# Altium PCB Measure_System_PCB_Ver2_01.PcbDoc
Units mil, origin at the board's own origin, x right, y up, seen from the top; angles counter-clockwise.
Board outline 2670.03 x 2130.03 mil, 2 copper layers (Top Layer, Bottom Layer); 49 components, 31 nets, 143 pads, 4 vias.
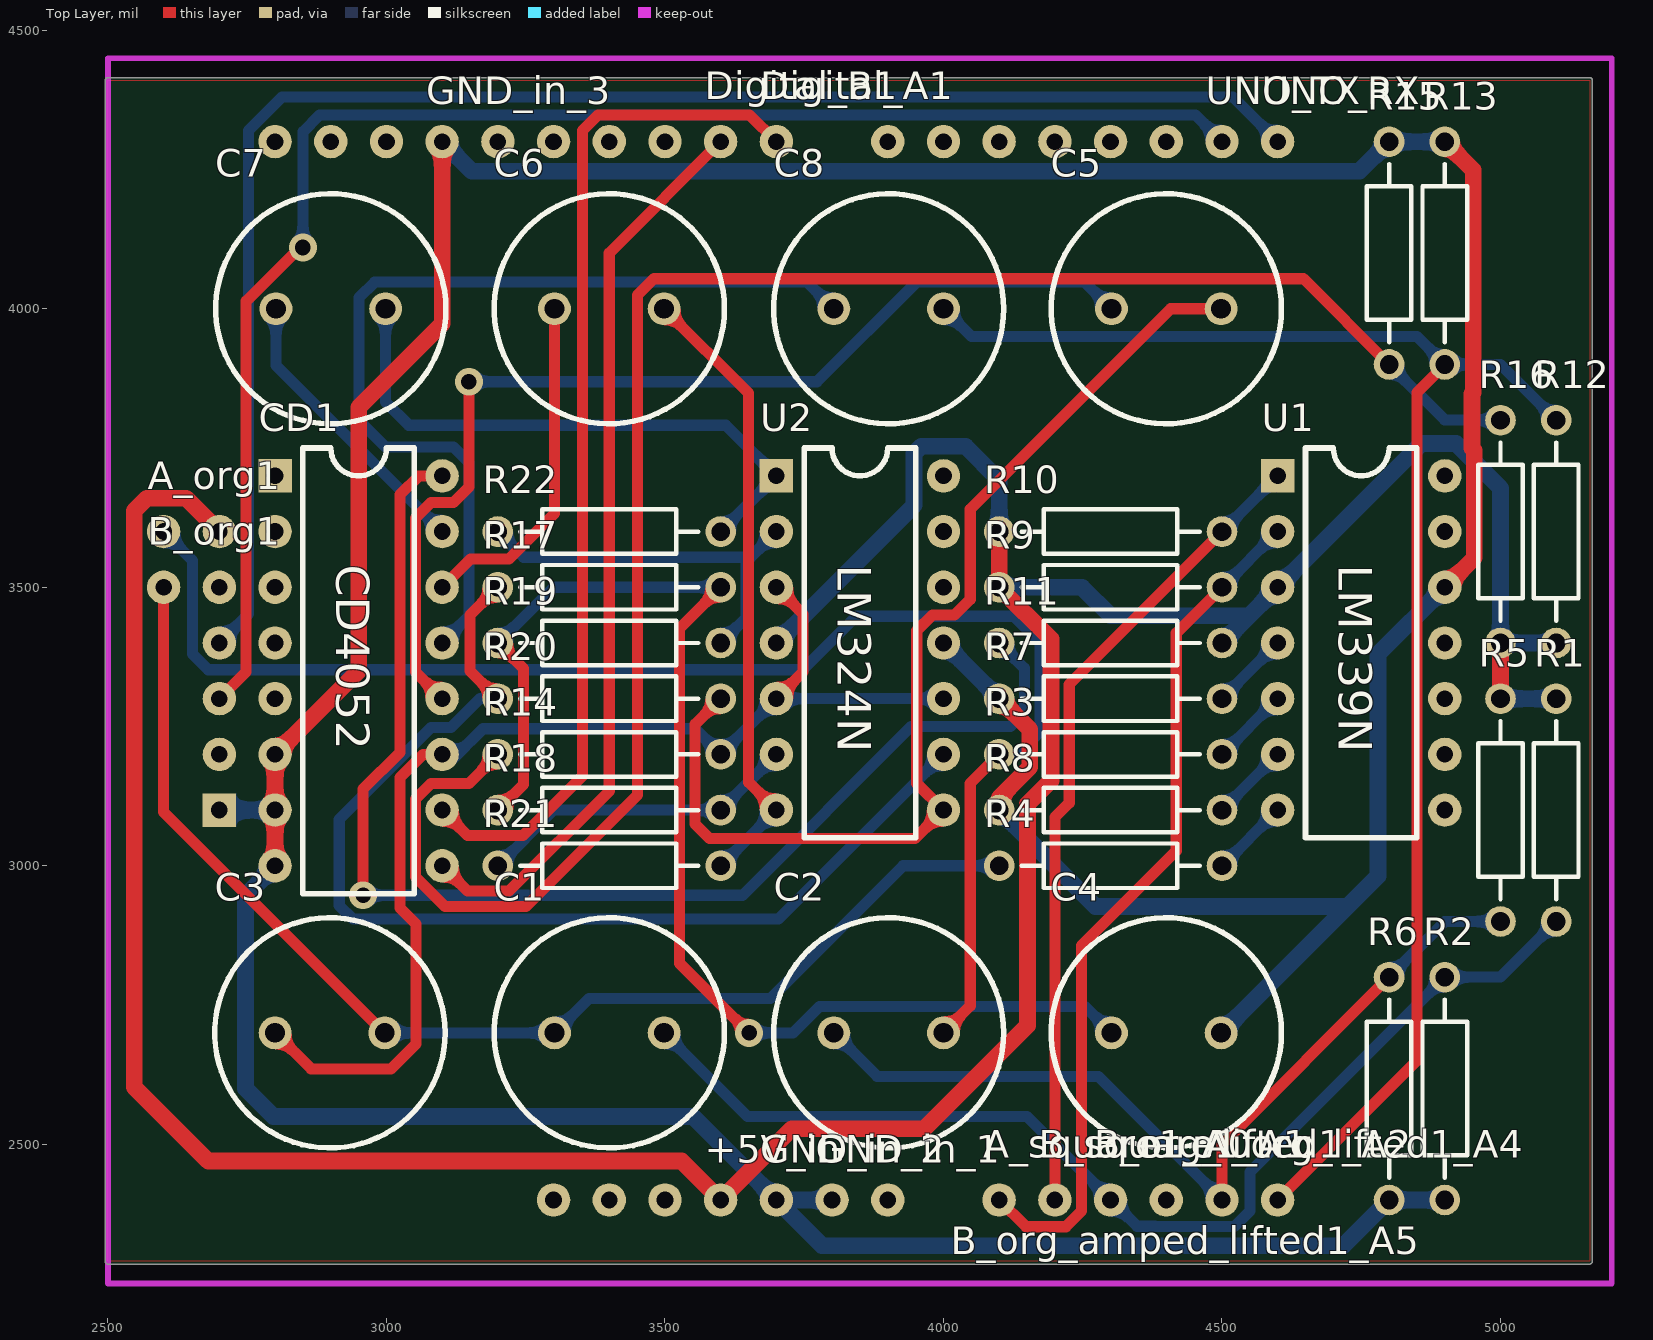
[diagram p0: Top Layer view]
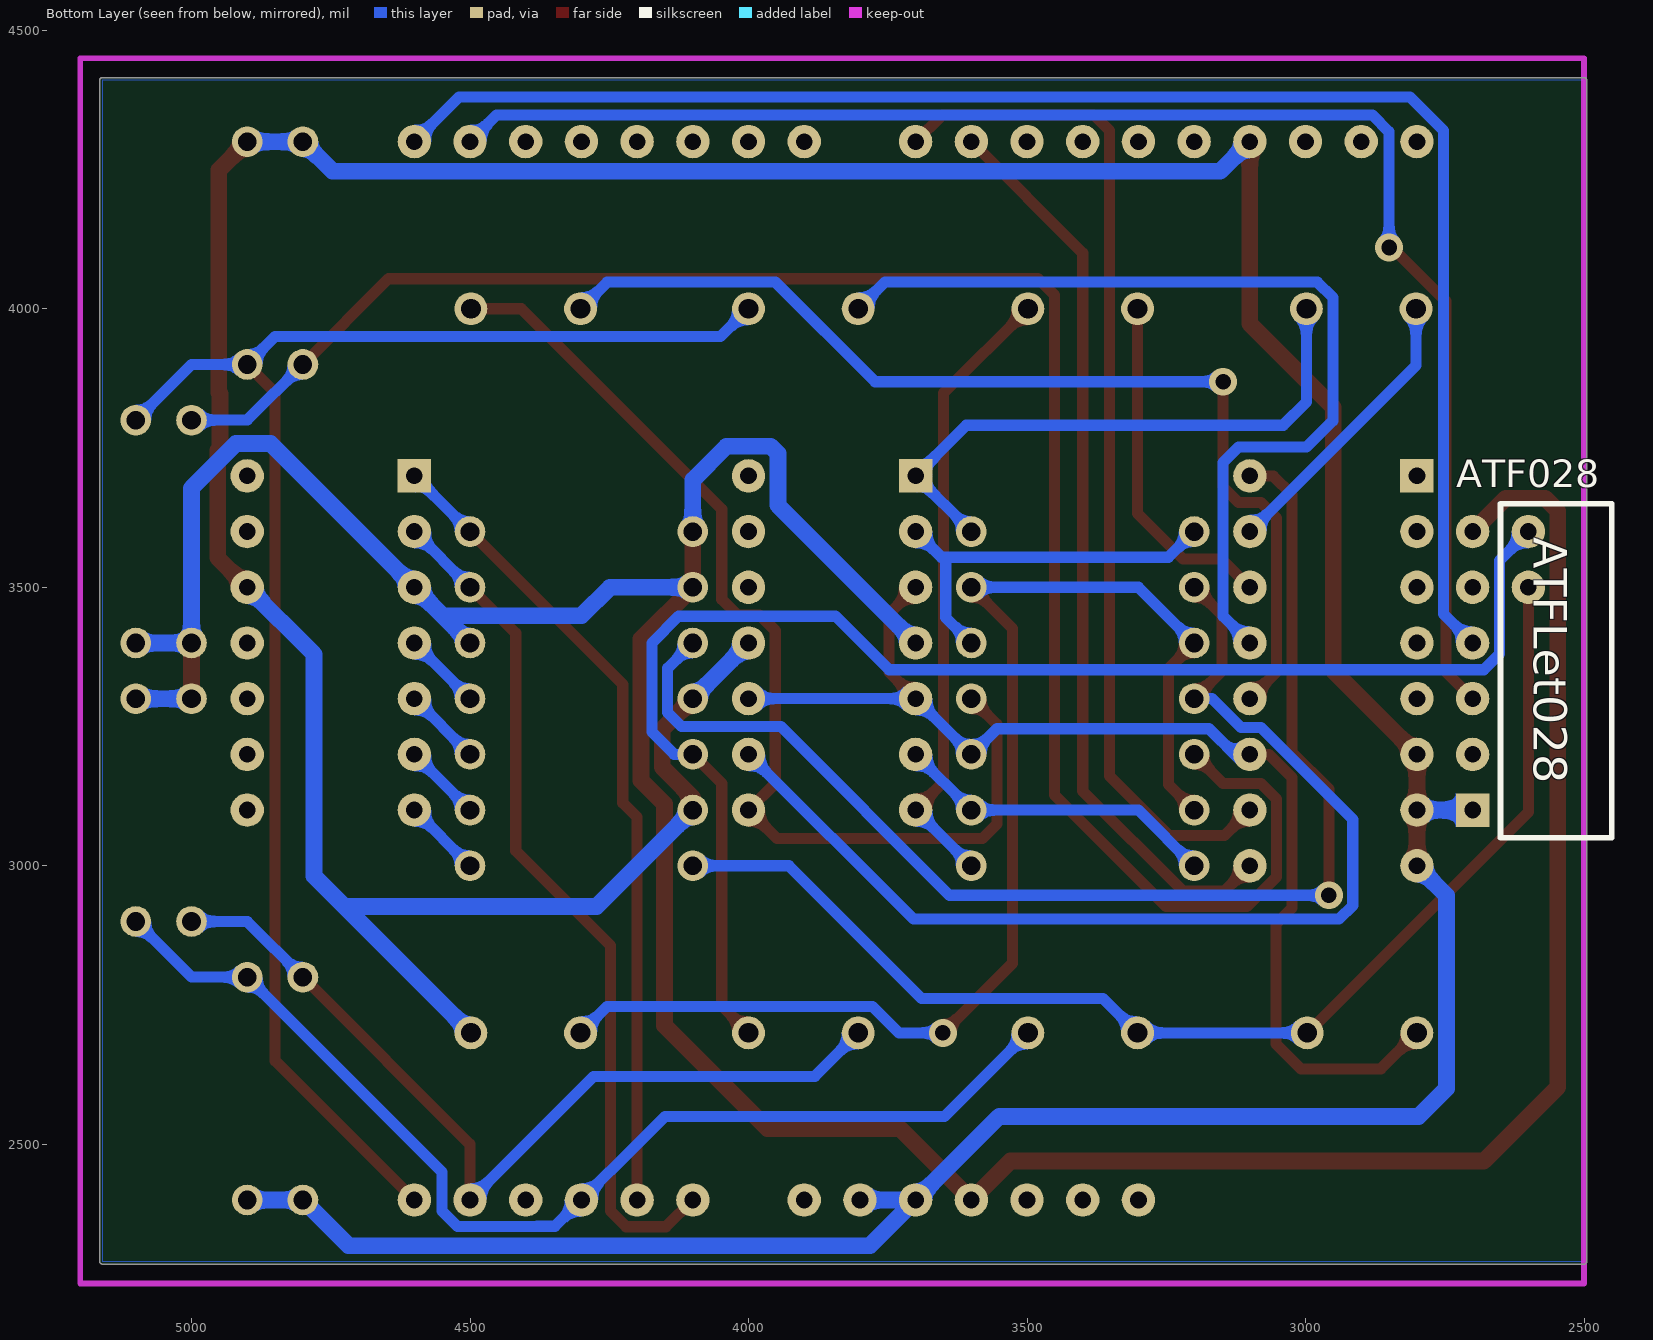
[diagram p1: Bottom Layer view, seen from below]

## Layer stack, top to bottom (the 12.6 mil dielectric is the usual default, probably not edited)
Top Solder: solder mask 0.4, Solder Resist, Dk 3.5
Top Layer: signal copper 1.4
Dielectric 1: dielectric 12.6, FR-4, Dk 4.8
Bottom Layer: signal copper 1.4
Bottom Solder: solder mask 0.4, Solder Resist, Dk 3.5

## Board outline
2494.99,2290 ccw(c2500,2290) 2500,2284.99 5160,2284.99 ccw(c5160,2290) 5165.02,2290 5165.02,4410 ccw(c5160,4410) 5160,4415.02 2500,4415.02 ccw(c2500,4410) 2494.99,4410

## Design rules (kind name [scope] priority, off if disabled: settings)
Clearance [All] p1: gap=7.87 ignorepadtopadclearanceinfootprint=FALSE
PolygonConnect [All] p1: connectstyle=Relief reliefconductorwidth=10 reliefentries=4 polygonreliefangle="90 Angle" airgapwidth=10
RoutingVias [All] p1: holewidth=28 width=50 viastyle="Through Hole" minholewidth=28 minwidth=50 maxholewidth=28 maxwidth=50
SolderMaskExpansion [All] p1: expansion=4 istentingtop=FALSE
Width Width_2 [InNet('GND')] p1: maxlimit=50 minlimit=10 preferedwidth=30 minimp=50.000000 maximp=50.000000 favimp=50.000000
Width Width_1 [InNet('+5')] p2: maxlimit=50 minlimit=10 preferedwidth=30 minimp=50.000000 maximp=50.000000 favimp=50.000000
Width [All] p3: maxlimit=50 minlimit=10 preferedwidth=20
30 further rules are at their usual default settings.

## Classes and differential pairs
component class Part_Square: C1 C2 R1 R2 R3 R4 R5 R6 R7 R8 R9 R10 U1
component class Part_PGA: C3 C4 C5 C6 C7 C8 CD1 R11 R12 R13 R14 R15 R16 R17 R18 R19 R20 R21 R22 U2
component class Measure_System_Main: +5V_in A_org1 A_org_lifted1_A4 A_square1_A0 ATF028 B_org1 B_org_amped_lifted1_A5 B_org_lifted1_A2 B_square1_A1 Digital_A1 Digital_B1 GND_in_1 GND_in_2 GND_in_3 UNO_RX UNO_TX

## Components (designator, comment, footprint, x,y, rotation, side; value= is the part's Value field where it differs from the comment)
+5V_in "Hole" Hole 3600,2400 r90 top
A_org1 "Hole" Hole 2600,3600 r90 top
A_org_lifted1_A4 "Hole" Hole 4500,2400 r90 top
A_square1_A0 "Hole" Hole 4100,2400 r90 top
ATF028 "ATFLet028" ATFLet028 2700,3600 r180 bottom
B_org1 "Hole" Hole 2600,3500 r90 top
B_org_amped_lifted1_A5 "Hole" Hole 4600,2400 r90 top
B_org_lifted1_A2 "Hole" Hole 4300,2400 r90 top
B_square1_A1 "Hole" Hole 4200,2400 r90 top
C1 "Cap Pol1" RB5-10.5 3400,2700 r0 top value=10u
C2 "Cap Pol1" RB5-10.5 3901.58,2700 r180 top value=10u
C3 "Cap Pol1" RB5-10.5 2898.43,2700 r180 top value=10u
C4 "Cap Pol1" RB5-10.5 4400,2700 r180 top value=10u
C5 "Cap Pol1" RB5-10.5 4400,4000 r180 top value=10u
C6 "Cap Pol1" RB5-10.5 3400,4000 r180 top value=10u
C7 "Cap Pol1" RB5-10.5 2900,4000 r180 top value=10u
C8 "Cap Pol1" RB5-10.5 3901.57,4000 r0 top value=10u
CD1 "CD4052" CD4052 2800,3700 r0 top
Digital_A1 "Hole" Hole 3700,4300 r90 top
Digital_B1 "Hole" Hole 3600,4300 r90 top
GND_in_1 "Hole" Hole 3800,2400 r90 top
GND_in_2 "Hole" Hole 3700,2400 r90 top
GND_in_3 "Hole" Hole 3100,4300 r90 top
R1 "Res2" AXIAL-0.4 5100,3100 r90 top value=100k
R2 "Res2" AXIAL-0.4 4900,2600 r90 top value=100k
R3 "Res2" AXIAL-0.4 4300,3200 r180 top value=1k
R4 "Res2" AXIAL-0.4 4300,3000 r180 top value=1k
R5 "Res2" AXIAL-0.4 5000,3100 r90 top value=100k
R6 "Res2" AXIAL-0.4 4800,2600 r90 top value=100k
R7 "Res2" AXIAL-0.4 4300,3300 r0 top value=10k
R8 "Res2" AXIAL-0.4 4300,3100 r180 top value=10k
R9 "Res2" AXIAL-0.4 4300,3500 r0 top value=10k
R10 "Res2" AXIAL-0.4 4300,3600 r180 top value=10k
R11 "Res2" AXIAL-0.4 4300,3400 r0 top value=200
R12 "Res2" AXIAL-0.4 5100,3600 r270 top value=100k
R13 "Res2" AXIAL-0.4 4900,4100 r270 top value=100k
R14 "Res2" AXIAL-0.4 3400,3200 r0 top value=100k
R15 "Res2" AXIAL-0.4 4800,4100 r270 top value=100k
R16 "Res2" AXIAL-0.4 5000,3600 r90 top value=100k
R17 "Res2" AXIAL-0.4 3400,3500 r180 top value=50k
R18 "Res2" AXIAL-0.4 3400,3100 r0 top value=24k
R19 "Res2" AXIAL-0.4 3400,3400 r0 top value=12k
R20 "Res2" AXIAL-0.4 3400,3300 r0 top value=100k
R21 "Res2" AXIAL-0.4 3400,3000 r0 top value=100k
R22 "Res2" AXIAL-0.4 3400,3600 r0 top value=100k
U1 "LM339N" LM339N 4600,3700 r0 top
U2 "LM324N" LM324N 3700,3700 r0 top
UNO_RX "Hole" Hole 4600,4300 r90 top
UNO_TX "Hole" Hole 4500,4300 r90 top

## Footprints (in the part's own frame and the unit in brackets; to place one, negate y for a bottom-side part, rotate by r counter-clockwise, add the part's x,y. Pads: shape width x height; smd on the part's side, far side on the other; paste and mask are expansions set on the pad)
ATFLet028 [mil]
  rect 60x60 hole 30: 1(0,-500)
  round 60 hole 30 mask+4: 2(0,-400) 3(0,-300) 4(0,-200) 5(0,-100) 6(0,0)
  silkscreen extent 50,-550 250,50
AXIAL-0.4 [mm] "Axial Device, Thru-Hole; 2 Leads; 0.4 in Pin Spacing"
  round 1.4 hole 0.85: 1(-5.08,0) 2(5.08,0)
  silkscreen extent -4.06,-1.02 4.06,1.02
CD4052 [mil]
  rect 60x60 hole 30: 1(0,0)
  round 60 hole 30 mask+4: 2(0,-100) 3(0,-200) 4(0,-300) 5(0,-400) 6(0,-500) 7(0,-600) 8(0,-700) 9(300,-700) 10(300,-600) 11(300,-500) 12(300,-400) 13(300,-300) 14(300,-200) 15(300,-100) 16(300,0)
  silkscreen extent 50,-750 250,50
Hole [mil]
  round 60 hole 30 mask+4: 1(0,0)
LM324N [mil]
  rect 60x60 hole 30: 1(0,0)
  round 60 hole 30 mask+4: 2(0,-100) 3(0,-200) 4(0,-300) 5(0,-400) 6(0,-500) 7(0,-600) 8(300,-600) 9(300,-500) 10(300,-400) 11(300,-300) 12(300,-200) 13(300,-100) 14(300,0)
  silkscreen extent 50,-650 250,50
LM339N [mil]
  rect 60x60 hole 30: 1(0,0)
  round 60 hole 30 mask+4: 2(0,-100) 3(0,-200) 4(0,-300) 5(0,-400) 6(0,-500) 7(0,-600) 8(300,-600) 9(300,-500) 10(300,-400) 11(300,-300) 12(300,-200) 13(300,-100) 14(300,0)
  silkscreen extent 50,-650 250,50
RB5-10.5 [mm] "Capacitor (Radial); 2 Leads"
  round 1.5 hole 0.9: 1(-2.5,0) 2(2.5,0)
  silkscreen extent -5.25,-5.25 5.25,5.25

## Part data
C1 C2 C3 C4 C5 C6 C7 C8: "Polarized Capacitor (Radial)"
R1 R2 R3 R4 R5 R6 R7 R8 R9 R10 R11 R12 R13 R14 R15 R16 R17 R18 R19 R20 R21 R22: "Resistor"

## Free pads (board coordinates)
  round 60 hole 30 mask+4: 5(4400,2400) 7(3900,2400) 8(3500,2400) 9(3400,2400) 10(3300,2400) 11(4400,4300) 12(4300,4300) 13(4200,4300) 14(4100,4300) 15(4000,4300) 16(3900,4300) 17(3500,4300) 18(3400,4300) 19(3300,4300) 20(3200,4300) 22(3000,4300) 23(2900,4300) 24(2800,4300)

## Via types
v1: diameter 50, hole 28, Top Layer to Bottom Layer, 4 vias

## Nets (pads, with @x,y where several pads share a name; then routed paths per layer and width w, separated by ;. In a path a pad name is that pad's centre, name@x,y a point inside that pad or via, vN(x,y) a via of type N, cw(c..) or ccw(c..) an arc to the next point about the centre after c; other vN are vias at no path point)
+5: +5V_in.1 ATF028.6 R1.2 R5.2 R9.1 R10.2 R11.2 R12.2 R16.1 U1.3 U2.4 | length 6430
  Top Layer w30: ATF028.6 2640,3660 2570,3660 2547,3637 2547,2603 2680,2470 3530,2470 +5V_in.1 3728,2528 3966,2528 4151,2713 4151,3111 4192.87,3152.87 4192.87,3407.13 R9.1 R10.2 ; R5.2 R16.1
  Bottom Layer w30: U2.4 3947,3647 3947,3740 3960,3753 4040,3753 4100,3693 R10.2 ; R9.1 4249,3500 4300,3449 4549,3449 ; R11.2 4549,3449 ; R5.2 R1.2 ; R12.2 R16.1 5000,3678 4920,3758 4858,3758 U1.3 4549,3449
B_org: B_org1.1 C1.1 C3.1 R4.2 | length 2191.8
  Top Layer w20: B_org1.1 2600,3096.85 C3.1
  Bottom Layer w20: C3.1 C1.1 3363.57,2762 3689.32,2762 3927.32,3000 R4.2
B_org_amp_1: C3.2 CD1.11 R14.2 U2.3 U2.5 U2.10 | length 2101.1
  Top Layer w20: C3.2 2865,2635 3008,2635 3053,2680 3053,2895.25 3024.25,2924 3024.25,3158.25 3066,3200 CD1.11 ; U2.5 3748,3348 3748,3452 U2.3
  Bottom Layer w20: CD1.11 3127,3200 3173,3246 3554,3246 R14.2 U2.5 U2.10
B_org_amp_2.5: C5.2 CD1.12 | length 1899.6
  Top Layer w20: CD1.12 3052.13,3347.87 3052.13,3624.13 3080,3652 3120,3652 3148,3680 v1(3148,3869)
  Bottom Layer w20: v1(3148,3869) 3773,3869 3952,4048 4253.57,4048 C5.2
B_org_amp_5: C6.2 CD1.14 | length 623.9
  Top Layer w20: CD1.14 3151,3551 3220,3551 3301.57,3632.57 C6.2
B_org_amp_10: C7.2 CD1.15 | length 523.6
  Bottom Layer w20: C7.2 2801.58,3898.42 CD1.15
B_org_amped: C8.1 CD1.13 | length 1676.6
  Bottom Layer w20: CD1.13 3148,3448 3148,3724 3120,3752 2998,3752 2951,3799 2951,4020 2979,4048 3755.15,4048 C8.1
Digital_A: CD1.10 Digital_A1.1 | length 1853.1
  Top Layer w20: CD1.10 3145.43,3054.57 3245,3054.57 3352,3161.57 3352,4320 3380,4348 3652,4348 Digital_A1.1
Digital_B: CD1.9 Digital_B1.1 | length 1641.7
  Top Layer w20: CD1.9 3145.43,2954.57 3220,2954.57 3400,3134.57 3400,4100 Digital_B1.1
GND: ATF028.1 C4.1 CD1.6 CD1.7 CD1.8 GND_in_1.1 GND_in_2.1 GND_in_3.1 R2.1 R6.1 R7.1 R8.2 R13.1 R15.1 U1.12 U2.11 | length 9089.9
  Top Layer w30: CD1.8 CD1.7 CD1.6 2950,3350 2950,3823 3100,3973 GND_in_3.1 ; R8.2 4100,3122 4155,3177 4155,3245 R7.1 ; U1.12 4953,3553 4953,3746 4949,3750 4949,3847 4951,3849 4951,4249 R13.1
  Bottom Layer w30: ATF028.1 CD1.7 ; CD1.8 2747,2947 2747,2600 2797,2550 3550,2550 GND_in_2.1 ; GND_in_3.1 3153,4247 4747,4247 R15.1 R13.1 ; GND_in_1.1 GND_in_2.1 ; U2.11 R7.1 ; R8.2 4273,2927 4725.43,2927 ; C4.1 4725.43,2927 ; R2.1 R6.1 4718,2318 3782,2318 GND_in_2.1 ; U1.12 4780,3380 4780,2981.57 4725.43,2927
NetA_org1_1: A_org1.1 C2.1 R3.2 | length 2625.4
  Top Layer w20: C2.1 4048,2748 4048,3148 R3.2
  Bottom Layer w20: A_org1.1 2652,3548 2652,3380 2680,3352 3748,3352 3844,3448 4125.31,3448 4173.31,3400 4173.31,3240 4133.31,3200 R3.2
NetA_org_lifted1_A4_1: A_org_lifted1_A4.1 C2.2 R5.1 R6.2 | length 1586.8
  Top Layer w20: A_org_lifted1_A4.1 4500,2500 R6.2
  Bottom Layer w20: C2.2 3881.15,2622 4278,2622 A_org_lifted1_A4.1 ; R6.2 4900,2900 R5.1
NetA_square1_A0_1: A_square1_A0.1 R9.2 U1.2 | length 1545.3
  Top Layer w20: A_square1_A0.1 4148,2352 4220,2352 4248,2380 4248,2857 4418,3027 4418,3418 R9.2
  Bottom Layer w20: R9.2 U1.2
NetATF028_3: ATF028.3 UNO_TX.1 | length 2765.4
  Top Layer w20: ATF028.3 2748,3348 2748,4013.46 2844.54,4110 v1(2850,4110)
  Bottom Layer w20: v1(2850,4110) 2850,4317.7 2880.17,4347.87 4452.13,4347.87 UNO_TX.1
NetATF028_4: ATF028.4 UNO_RX.1 | length 2847.4
  Bottom Layer w20: ATF028.4 2752.13,3452.13 2752.13,4319.83 2812.3,4380 4520,4380 UNO_RX.1
NetB_org_amped_lifted1_A5_1: B_org_amped_lifted1_A5.1 C8.2 R12.1 R13.2 | length 2807.1
  Top Layer w20: B_org_amped_lifted1_A5.1 4850,2650 4850,3850 R13.2
  Bottom Layer w20: C8.2 4050,3950 4850,3950 R13.2 5000,3900 R12.1
NetB_org_lifted1_A2_1: B_org_lifted1_A2.1 C1.2 R1.1 R2.2 | length 2013.6
  Bottom Layer w20: C1.2 3648.43,2550 4150,2550 4347.13,2352.87 4379.42,2352.87 4380.17,2352.13 4522.13,2352.13 4550,2380 4550,2450 R2.2 5000,2800 R1.1
NetB_square1_A1_1: B_square1_A1.1 R10.1 U1.1 | length 1465.7
  Top Layer w20: B_square1_A1.1 4200,3087.25 4225.75,3113 4225.75,3325.75 R10.1
  Bottom Layer w20: R10.1 U1.1
NetC4_2: C4.2 R17.1 R18.1 R19.1 | length 2351.8
  Top Layer w20: R18.1 3246,3146 3246,3354 R19.1 ; R17.1 3526,3426 3526,2825 v1(3651,2700)
  Bottom Layer w20: R19.1 3300,3500 R17.1 ; v1(3651,2700) 3730,2700 3777.4,2747.4 4254.17,2747.4 C4.2
NetC5_1: C5.1 R20.2 U2.8 | length 1944.6
  Top Layer w20: R20.2 3554,3254 3554,3075 3580,3049 3949,3049 U2.8 3952,3148 3952,3422 3980,3450 4020,3450 4048,3478 4048,3640 4408,4000 C5.1
NetC6_1: C6.1 R21.2 U2.7 | length 1124.9
  Top Layer w20: C6.1 3650,3848.43 3650,3150 U2.7
  Bottom Layer w20: R21.2 U2.7
NetC7_1: C7.1 R22.2 U2.1 | length 1065.3
  Bottom Layer w20: C7.1 2998.43,3832.57 3040,3791 3609,3791 U2.1 R22.2
NetCD1_16: CD1.16 R11.1 | length 2303.3
  Top Layer w20: v1(2958,2947) 2958,3137.5 3024.25,3203.75 3024.25,3666.25 3058,3700 CD1.16
  Bottom Layer w20: v1(2958,2947) 3639,2947 3942,3250 4120,3250 4145.43,3275.43 4145.43,3354.57 R11.1
NetR3_1: R3.1 U1.5 | length 141.4
  Bottom Layer w20: R3.1 U1.5
NetR4_1: R4.1 U1.7 | length 141.4
  Bottom Layer w20: R4.1 U1.7
NetR7_2: R7.2 U1.4 | length 141.4
  Bottom Layer w20: R7.2 U1.4
NetR8_1: R8.1 U1.6 | length 141.4
  Bottom Layer w20: R8.1 U1.6
NetR14_1: R14.1 R15.2 R16.2 | length 3389.3
  Top Layer w20: R14.1 3148,3148 3080,3148 3052.13,3120.13 3052.13,2979.87 3105.31,2926.69 3250.69,2926.69 3451,3127 3451,4025 3480,4054 4646,4054 R15.2
  Bottom Layer w20: R15.2 4900,3800 R16.2
NetR17_2: R17.2 R20.1 U2.9 | length 1988
  Top Layer w20: R20.1 3150,3350 3150,3450 R17.2
  Bottom Layer w20: R20.1 3167.71,3300 3115.71,3248 3080,3248 2915.13,3083.13 2915.13,2929 2940,2904.13 3704.13,2904.13 U2.9
NetR18_2: R18.2 R21.1 U2.6 | length 582.8
  Bottom Layer w20: R21.1 3300,3100 R18.2 U2.6
NetR19_2: R19.2 R22.1 U2.2 | length 711.2
  Bottom Layer w20: R22.1 3246,3554 3646,3554 ; R19.2 3646,3446 3646,3554 ; U2.2 3654,3554 3646,3554
pads on no net: ATF028.2 ATF028.5 CD1.1 CD1.2 CD1.3 CD1.4 CD1.5 U1.8 U1.9 U1.10 U1.11 U1.13 U1.14 U2.12 U2.13 U2.14

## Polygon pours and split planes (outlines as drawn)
GND on Top Layer "NONET_L-01_P-001" (solid, remove dead copper, shelved, pour order 0): 2500,4410 5160,4410 5160,2290 2500,2290
GND on Bottom Layer "NONET_L-01_P-001" (solid, remove dead copper, shelved, pour order 1): 2500,4410 5160,4410 5160,2290 2500,2290

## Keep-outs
Keep-Out Layer:
  lines w10: 2500,2250 2500,4450 5200,4450 5200,2250 2500,2250

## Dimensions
5160,4415.02 to 5165.02,2290 on Top Layer
2494.99,4410 to 5160,4415.02 on Top Layer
